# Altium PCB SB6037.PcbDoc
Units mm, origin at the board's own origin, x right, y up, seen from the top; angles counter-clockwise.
Board outline 60 x 37 mm, 2 copper layers (Top Layer, Bottom Layer); 0 components, 0 nets, 4 pads, 0 vias.
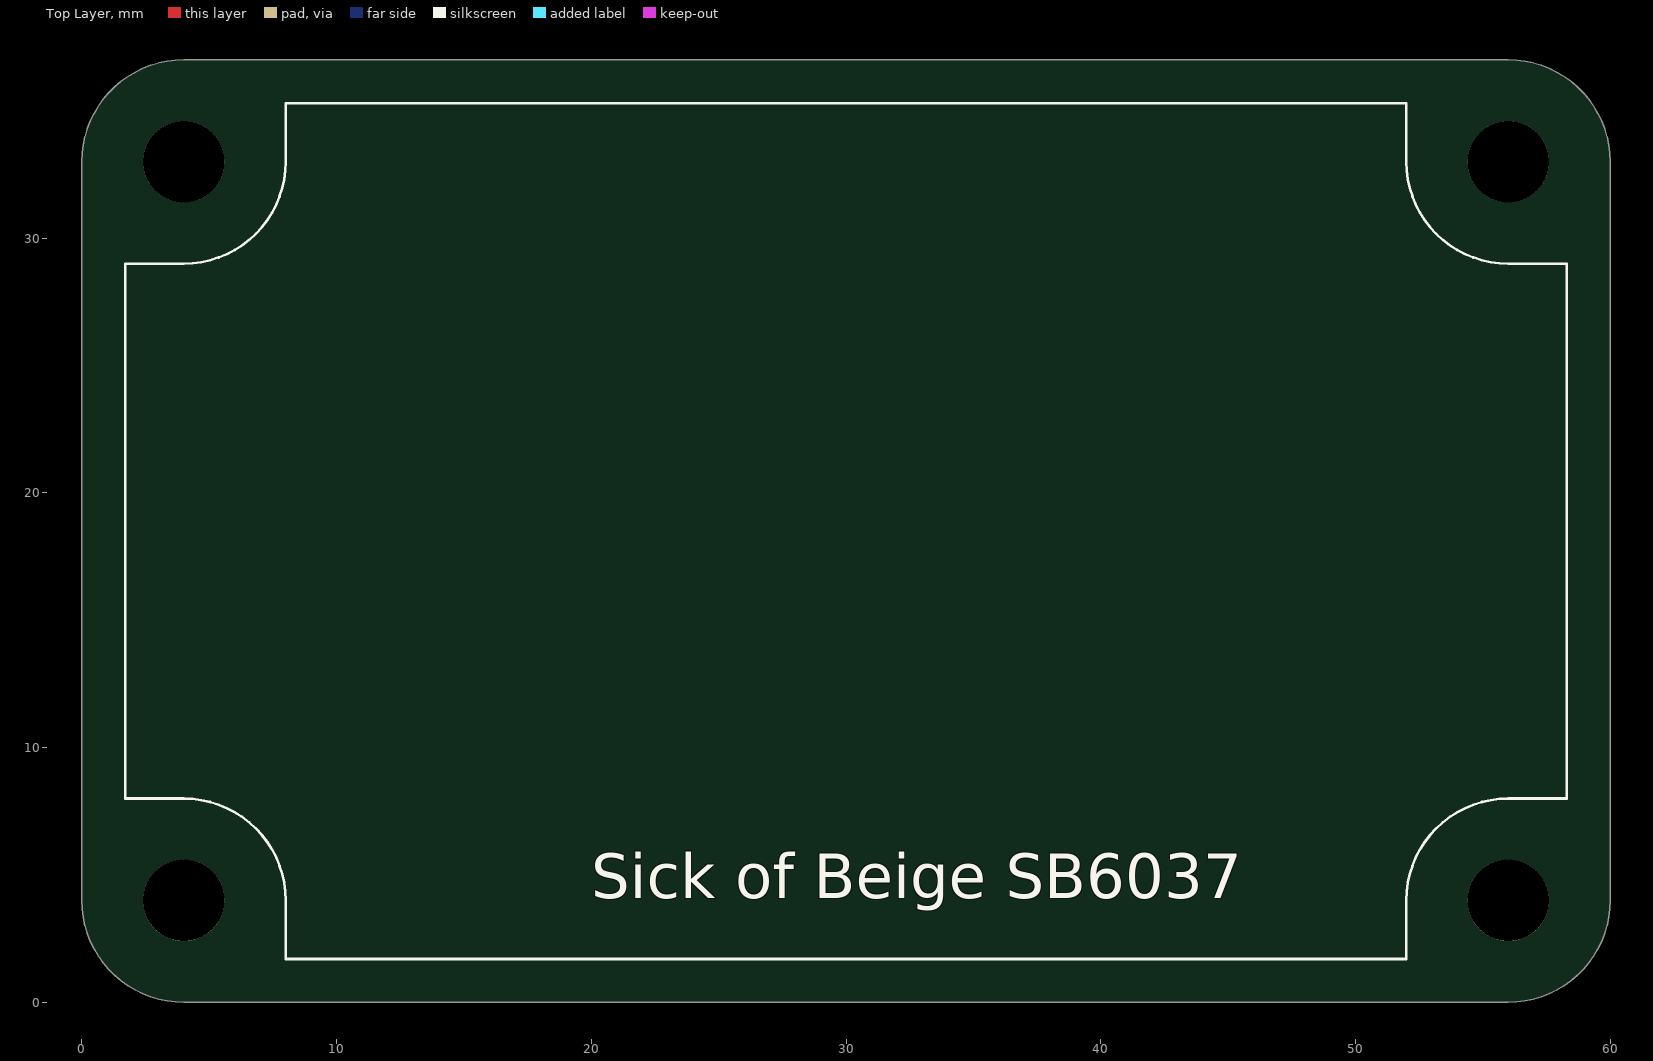
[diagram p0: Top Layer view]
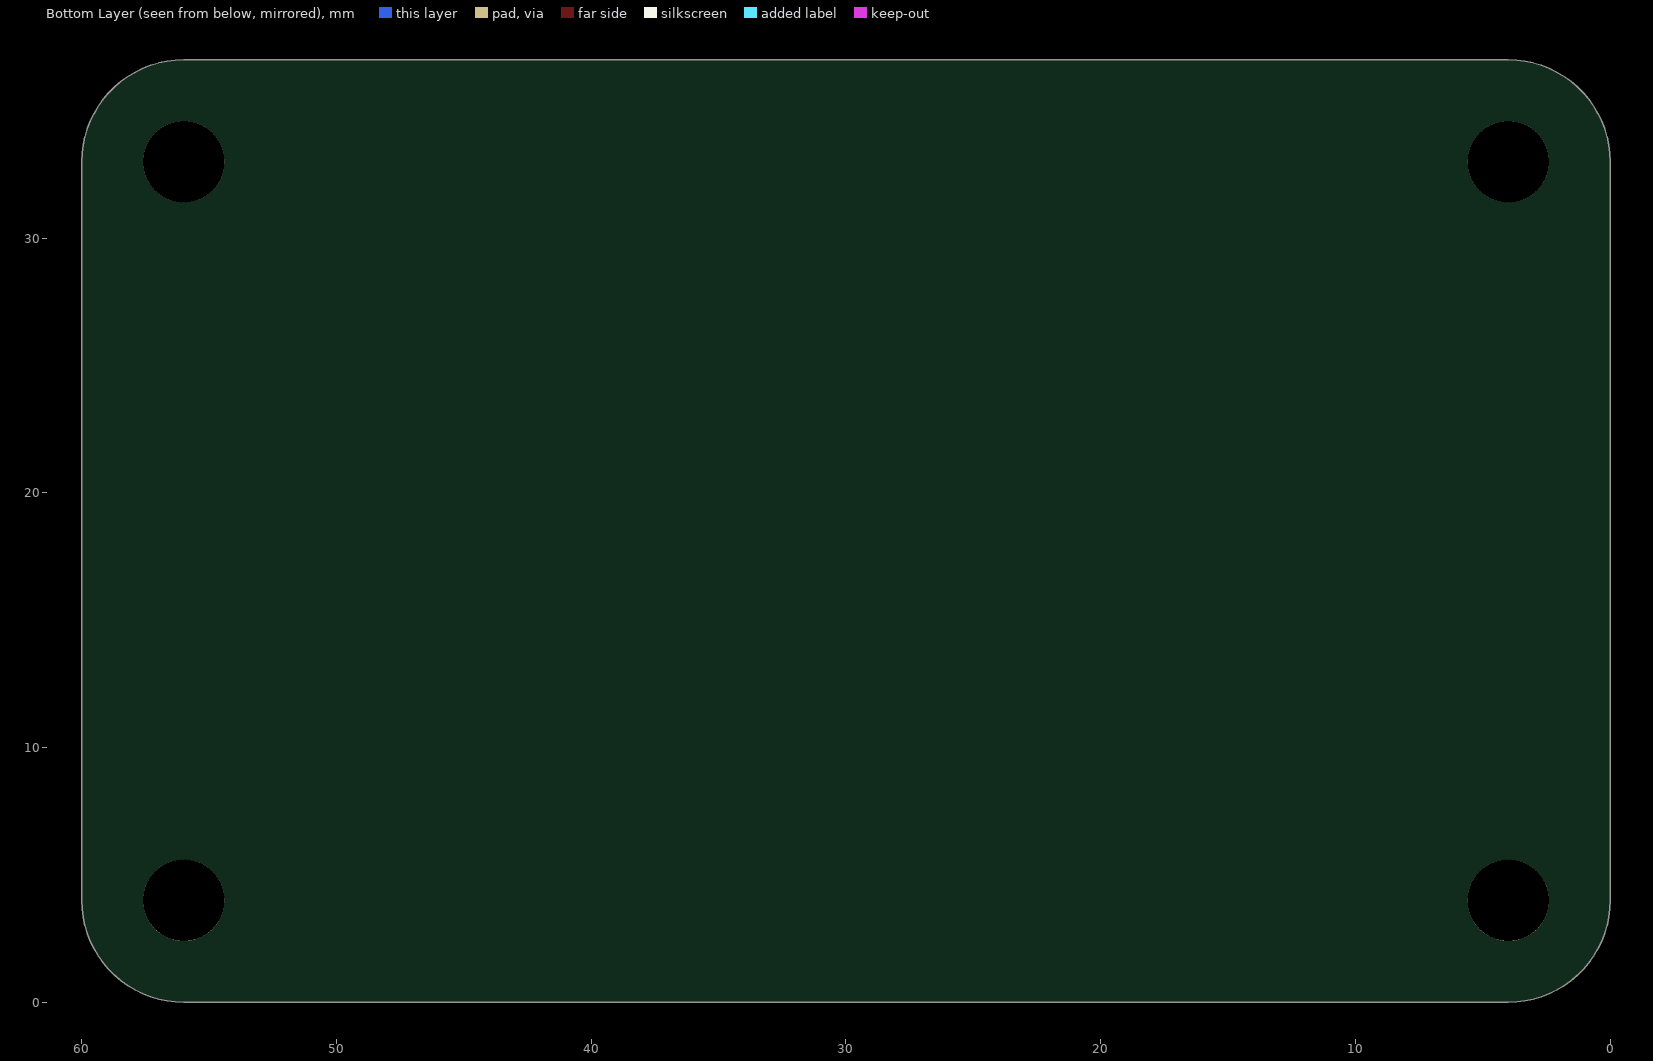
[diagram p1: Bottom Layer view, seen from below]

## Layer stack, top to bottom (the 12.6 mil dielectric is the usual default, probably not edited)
Top Layer: signal copper 0.0356
Dielectric: dielectric 0.32, FR-4, Dk 4.8
Bottom Layer: signal copper 0.0356

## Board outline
0,4 0,33 cw(c4,33) 4,37 56,37 cw(c56,33) 60,33 60,4 cw(c56,4) 56,0 4,0 cw(c4,4)

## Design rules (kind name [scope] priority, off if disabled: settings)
Clearance [All] p1: gap=0.254
PolygonConnect [All] p1: connectstyle=Relief reliefconductorwidth=0.254 reliefentries=4 polygonreliefangle="90 Angle" airgapwidth=0.254
RoutingVias [All] p1: holewidth=0.711 width=1.27 viastyle="Through Hole" minholewidth=0.711 minwidth=1.27 maxholewidth=0.711 maxwidth=1.27
SolderMaskExpansion [All] p1: expansion=0.102
Width [All] p1: maxlimit=0.254 minlimit=0.254 preferedwidth=0.254
28 further rules are at their usual default settings.

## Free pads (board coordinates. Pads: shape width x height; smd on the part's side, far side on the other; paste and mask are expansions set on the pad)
  round 3.2 hole 3.2 unplated: 0(4,4) 1(4,33) 2(56,33) 3(56,4)

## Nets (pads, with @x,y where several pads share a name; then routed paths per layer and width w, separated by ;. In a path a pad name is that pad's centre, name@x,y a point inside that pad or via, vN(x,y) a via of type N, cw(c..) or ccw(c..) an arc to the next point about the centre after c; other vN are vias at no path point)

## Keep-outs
Top Overlay:
  lines w0.102: 1.7,8 4,8 cw(c4,4) 8,4 8,1.7 52,1.7 52,4 cw(c56,4) 56,8 58.3,8 58.3,29 56,29 cw(c56,33) 52,33 52,35.3 8,35.3 8,33 cw(c4,33) 4,29 1.7,29 1.7,8

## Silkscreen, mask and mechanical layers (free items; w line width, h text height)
Top Overlay:
  text "Sick of Beige SB6037" at 20,3.5 h3
Mechanical 1:
  the board outline again, w0.102
Mechanical 4:
  circle w0.102: c56,4 r1.6
  circle w0.102: c4,4 r1.6
  circle w0.102: c4,33 r1.6
  circle w0.102: c56,33 r1.6
  lines w0.102: 0,18.5 60,18.5 ; 30,0 30,37

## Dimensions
56,37 to 56,0 on Mechanical 3
0,4 to 60,4 on Mechanical 3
